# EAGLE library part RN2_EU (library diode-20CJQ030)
Chip Resistor Array's from various manufactures
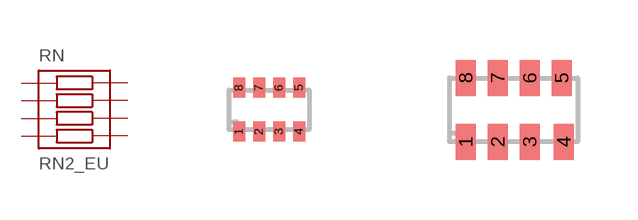
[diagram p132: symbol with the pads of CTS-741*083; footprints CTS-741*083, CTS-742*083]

Designator prefix RN

## RN2_EU-1  [CTS-741*083]
1  1  pas
2  2  pas
3  3  pas
4  4  pas
5  5  pas
6  6  pas
7  7  pas
8  8  pas

## RN2_EU-2  [CTS-742*083]
1  5  pas
2  3  pas
3  2  pas
4  1  pas
5  8  pas
6  7  pas
7  6  pas
8  4  pas

## RN2_EU-3  [CTS-743*083]
Pads as for CTS-742*083

## RN2_EU-4  [CTS-744*083]
Pads as for CTS-742*083

## RN2_EU-5  [EXB-28V]
Pads as for CTS-742*083

## RN2_EU-6  [EXB-38V]
Pads as for CTS-742*083

## RN2_EU-7  [EXB-V8V]
Pads as for CTS-742*083

## Footprint CTS-741*083 (pad centres in mm)
CTS Resistor Chip Arrays 402
smd 0.3 x 0.5: 1 -0.75,-0.55; 2 -0.25,-0.55; 3 0.25,-0.55; 4 0.75,-0.55; 5 0.75,0.55; 6 0.25,0.55; 7 -0.25,0.55; 8 -0.75,0.55

## Footprint CTS-742*083 (pad centres in mm)
CTS Resistor Chip Arrays 603
smd 0.5 x 0.9: 1 -1.2,-0.8; 2 -0.4,-0.8; 3 0.4,-0.8; 4 1.25,-0.8; 5 1.2,0.8; 6 0.4,0.8; 7 -0.4,0.8; 8 -1.2,0.8

## Footprint CTS-743*083 (pad centres in mm)
CTS Resistor Chip Arrays 805
smd 0.8 x 1: 1 -1.905,-1; 2 -0.635,-1; 3 0.635,-1; 4 1.905,-1; 5 1.905,1; 6 0.635,1; 7 -0.635,1; 8 -1.905,1

## Footprint CTS-744*083 (pad centres in mm)
CTS Resistor Chip Arrays 1206
smd 0.8 x 1: 1 -1.905,-1.6; 2 -0.635,-1.6; 3 0.635,-1.6; 4 1.905,-1.6; 5 1.905,1.6; 6 0.635,1.6; 7 -0.635,1.6; 8 -1.905,1.6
